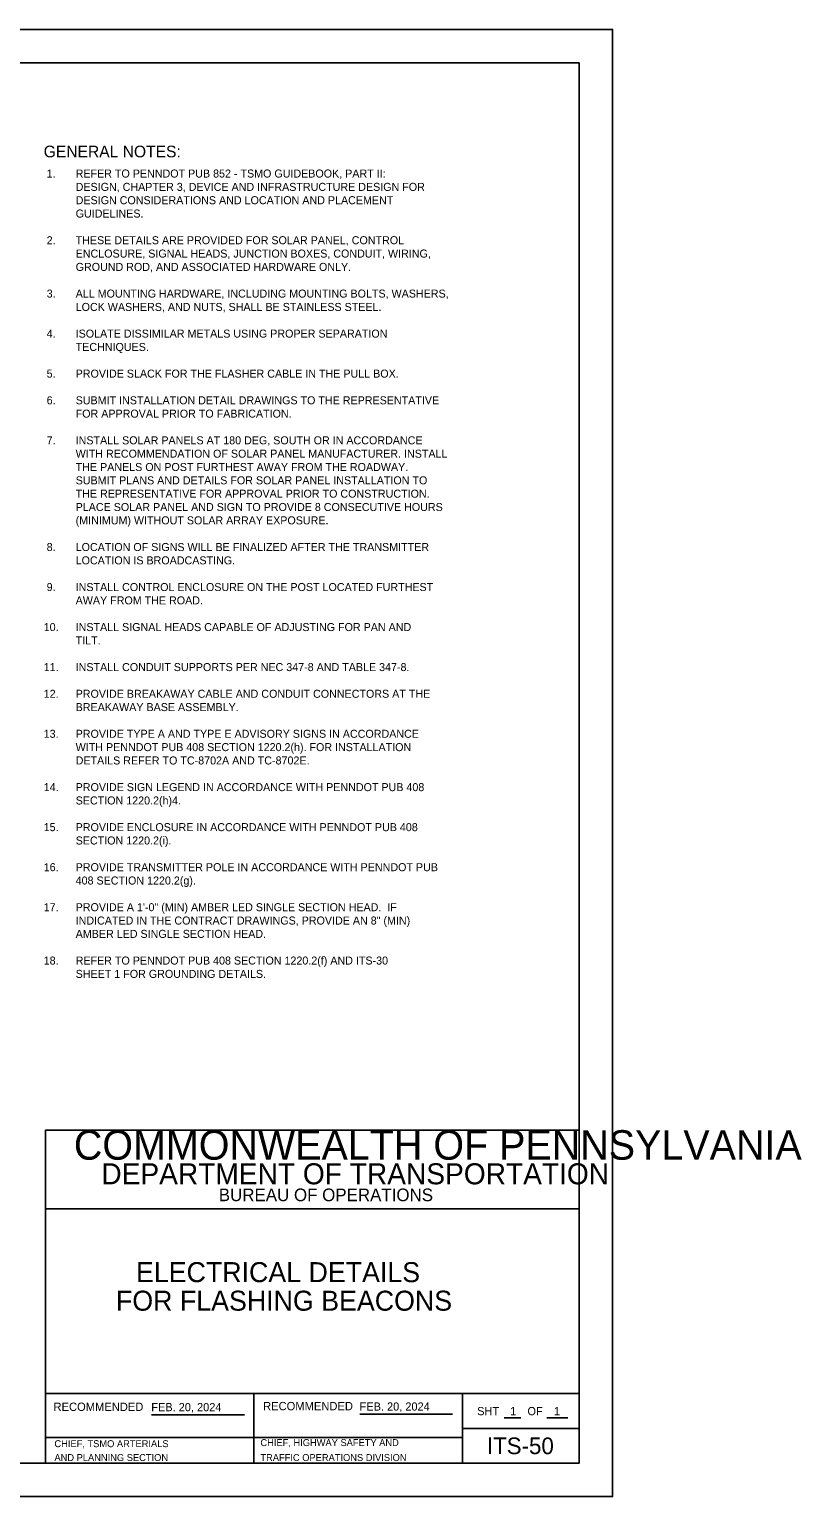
# Model space of a CAD drawing. Extents: x 1299104.6 to 1299141.5, y 239713.3 to 239735.3.
# Drawn here: x 1299129.88 to 1299141.46, y 239713.27 to 239735.27 of the extents above; entities that cross this region are included whole.
import ezdxf

# ---------------------------------------------------------------- set-up
doc = ezdxf.new("R2010")
doc.units = 0
for name, color, linetype in [('1', 7, 'Continuous'), ('2', 7, 'Continuous'), ('DIM TXT', 7, 'Continuous'), ('GS_noplot_1', 7, 'Continuous'), ('GS_plotshape_p', 7, 'Continuous'), ('Level 1', 7, 'Continuous'), ('PTEXT', 7, 'Continuous')]:
    doc.layers.add(name, color=color, linetype=linetype)

msp = doc.modelspace()

# ---------------------------------------------------------------- linework, layer by layer
at = {"layer": '1'}
for p, q in [((1299131.715, 239714.502), (1299133.105, 239714.502)), ((1299134.837, 239714.511), (1299136.226, 239714.511)), ((1299136.996, 239714.455), (1299137.248, 239714.455)), ((1299137.639, 239714.455), (1299137.953, 239714.455)), ((1299130.122, 239714.161), (1299133.247, 239714.161))]:
    msp.add_line(p, q, dxfattribs=at)
at = {"layer": 'GS_noplot_1'}
msp.add_lwpolyline([(1299130.122, 239714.821), (1299136.372, 239714.821), (1299136.372, 239713.773), (1299130.122, 239713.773)], close=True, dxfattribs=at)
at = {"layer": 'GS_plotshape_p'}
msp.add_lwpolyline([(1299104.622, 239735.273), (1299138.622, 239735.273), (1299138.622, 239713.273), (1299104.622, 239713.273)], close=True, dxfattribs=at)
at = {"layer": 'Level 1'}
for p, q in [((1299130.122, 239714.821), (1299138.122, 239714.821)), ((1299133.247, 239714.821), (1299133.247, 239713.773)), ((1299136.372, 239714.297), (1299138.122, 239714.297)), ((1299133.247, 239714.161), (1299136.372, 239714.161))]:
    msp.add_line(p, q, dxfattribs=at)
for points in [[(1299138.122, 239713.773), (1299106.122, 239713.773), (1299106.122, 239734.773), (1299138.122, 239734.773)], [(1299138.122, 239718.766), (1299130.122, 239718.766), (1299130.122, 239717.586), (1299138.122, 239717.586)], [(1299138.122, 239718.766), (1299130.122, 239718.766), (1299130.122, 239713.773), (1299138.122, 239713.773)]]:
    msp.add_lwpolyline(points, close=True, dxfattribs=at)

# ---------------------------------------------------------------- texts
at = {"layer": '1'}
for s, height, p in [('COMMONWEALTH OF PENNSYLVANIA', 0.44223, (1299130.549, 239718.325)), ('DEPARTMENT OF TRANSPORTATION', 0.31514, (1299130.961, 239717.956)), ('BUREAU OF OPERATIONS', 0.18955, (1299132.721, 239717.703)), ('RECOMMENDED', 0.125, (1299130.244, 239714.558)), ('FEB. 20, 2024', 0.12303, (1299131.709, 239714.554)), ('RECOMMENDED', 0.125, (1299133.385, 239714.568)), ('FEB. 20, 2024', 0.12303, (1299134.831, 239714.563)), ('CHIEF, TSMO ARTERIALS ', 0.10417, (1299130.258, 239714.015)), ('CHIEF, HIGHWAY SAFETY AND ', 0.10417, (1299133.345, 239714.031)), ('AND PLANNING SECTION', 0.10417, (1299130.258, 239713.807)), ('TRAFFIC OPERATIONS DIVISION', 0.10417, (1299133.345, 239713.807))]:
    msp.add_text(s, height=height, dxfattribs=at).set_placement(p)
at = {"layer": '2'}
for s, p in [('SHT', (1299136.593, 239714.494)), ('1', (1299137.087, 239714.494)), ('OF', (1299137.347, 239714.494)), ('1', (1299137.744, 239714.494))]:
    msp.add_text(s, height=0.123, dxfattribs=at).set_placement(p)
at = {"layer": 'DIM TXT'}
for s, p in [('REFER TO PENNDOT PUB 852 - TSMO GUIDEBOOK, PART II: ', (1299130.576, 239733.051)), ('DESIGN, CHAPTER 3, DEVICE AND INFRASTRUCTURE DESIGN FOR ', (1299130.576, 239732.851)), ('DESIGN CONSIDERATIONS AND LOCATION AND PLACEMENT ', (1299130.576, 239732.651)), ('GUIDELINES.', (1299130.576, 239732.451)), ('THESE DETAILS ARE PROVIDED FOR SOLAR PANEL, CONTROL ', (1299130.576, 239732.051)), ('ENCLOSURE, SIGNAL HEADS, JUNCTION BOXES, CONDUIT, WIRING, ', (1299130.576, 239731.851)), ('GROUND ROD, AND ASSOCIATED HARDWARE ONLY.', (1299130.576, 239731.651)), ('ALL MOUNTING HARDWARE, INCLUDING MOUNTING BOLTS, WASHERS, ', (1299130.576, 239731.251)), ('LOCK WASHERS, AND NUTS, SHALL BE STAINLESS STEEL. ', (1299130.576, 239731.051)), ('ISOLATE DISSIMILAR METALS USING PROPER SEPARATION ', (1299130.576, 239730.651)), ('TECHNIQUES.', (1299130.576, 239730.451)), ('PROVIDE SLACK FOR THE FLASHER CABLE IN THE PULL BOX. ', (1299130.576, 239730.051)), ('SUBMIT INSTALLATION DETAIL DRAWINGS TO THE REPRESENTATIVE ', (1299130.576, 239729.651)), ('FOR APPROVAL PRIOR TO FABRICATION. ', (1299130.576, 239729.451)), ('INSTALL SOLAR PANELS AT 180 DEG, SOUTH OR IN ACCORDANCE ', (1299130.576, 239729.051)), ('WITH RECOMMENDATION OF SOLAR PANEL MANUFACTURER. INSTALL ', (1299130.576, 239728.851)), ('THE PANELS ON POST FURTHEST AWAY FROM THE ROADWAY.  ', (1299130.576, 239728.651)), ('SUBMIT PLANS AND DETAILS FOR SOLAR PANEL INSTALLATION TO ', (1299130.576, 239728.451)), ('THE REPRESENTATIVE FOR APPROVAL PRIOR TO CONSTRUCTION. ', (1299130.576, 239728.251)), ('PLACE SOLAR PANEL AND SIGN TO PROVIDE 8 CONSECUTIVE HOURS ', (1299130.576, 239728.051)), ('(MINIMUM) WITHOUT SOLAR ARRAY EXPOSURE.', (1299130.576, 239727.851)), ('LOCATION OF SIGNS WILL BE FINALIZED AFTER THE TRANSMITTER ', (1299130.576, 239727.451)), ('LOCATION IS BROADCASTING. ', (1299130.576, 239727.251)), ('INSTALL CONTROL ENCLOSURE ON THE POST LOCATED FURTHEST ', (1299130.576, 239726.851)), ('AWAY FROM THE ROAD. ', (1299130.576, 239726.651)), ('INSTALL SIGNAL HEADS CAPABLE OF ADJUSTING FOR PAN AND ', (1299130.576, 239726.251)), ('TILT. ', (1299130.576, 239726.051)), ('INSTALL CONDUIT SUPPORTS PER NEC 347-8 AND TABLE 347-8. ', (1299130.576, 239725.651)), ('PROVIDE BREAKAWAY CABLE AND CONDUIT CONNECTORS AT THE ', (1299130.576, 239725.251)), ('BREAKAWAY BASE ASSEMBLY.', (1299130.576, 239725.051)), ('PROVIDE TYPE A AND TYPE E ADVISORY SIGNS IN ACCORDANCE ', (1299130.576, 239724.651)), ('WITH PENNDOT PUB 408 SECTION 1220.2(h). FOR INSTALLATION ', (1299130.576, 239724.451)), ('DETAILS REFER TO TC-8702A AND TC-8702E.', (1299130.576, 239724.251)), ('PROVIDE SIGN LEGEND IN ACCORDANCE WITH PENNDOT PUB 408 ', (1299130.576, 239723.851)), ('SECTION 1220.2(h)4.', (1299130.576, 239723.651)), ('PROVIDE ENCLOSURE IN ACCORDANCE WITH PENNDOT PUB 408 ', (1299130.576, 239723.251)), ('SECTION 1220.2(i).', (1299130.576, 239723.051)), ('408 SECTION 1220.2(g).', (1299130.576, 239722.451)), ('PROVIDE TRANSMITTER POLE IN ACCORDANCE WITH PENNDOT PUB ', (1299130.576, 239722.651)), ('PROVIDE A 1\'-0" (MIN) AMBER LED SINGLE SECTION HEAD.  IF ', (1299130.576, 239722.051)), ('INDICATED IN THE CONTRACT DRAWINGS, PROVIDE AN 8" (MIN) ', (1299130.576, 239721.851)), ('AMBER LED SINGLE SECTION HEAD.', (1299130.576, 239721.651)), ('REFER TO PENNDOT PUB 408 SECTION 1220.2(f) AND ITS-30 ', (1299130.576, 239721.251)), ('SHEET 1 FOR GROUNDING DETAILS.', (1299130.576, 239721.051))]:
    msp.add_text(s, height=0.12, dxfattribs=at).set_placement(p)
at = {"layer": 'PTEXT'}
for s, height, p in [('GENERAL NOTES:', 0.175, (1299130.097, 239733.354)), (' 1.', 0.12, (1299130.097, 239733.051)), (' 2.', 0.12, (1299130.097, 239732.051)), (' 3.', 0.12, (1299130.097, 239731.251)), (' 4. ', 0.12, (1299130.097, 239730.651)), (' 5.', 0.12, (1299130.097, 239730.051)), (' 6.', 0.12, (1299130.097, 239729.651)), (' 7.', 0.12, (1299130.097, 239729.051)), (' 8.', 0.12, (1299130.097, 239727.451)), (' 9.', 0.12, (1299130.097, 239726.851)), ('10.', 0.12, (1299130.097, 239726.251)), ('11.', 0.12, (1299130.097, 239725.651)), ('12.', 0.12, (1299130.097, 239725.251)), ('13.', 0.12, (1299130.097, 239724.651)), ('14.', 0.12, (1299130.097, 239723.851)), ('15.', 0.12, (1299130.097, 239723.251)), ('16.', 0.12, (1299130.097, 239722.651)), ('17.', 0.12, (1299130.097, 239722.051)), ('18.', 0.12, (1299130.097, 239721.251)), ('ELECTRICAL DETAILS', 0.3, (1299131.48, 239716.489)), ('FOR FLASHING BEACONS', 0.3, (1299131.18, 239716.061)), ('ITS-50', 0.25, (1299136.739, 239713.91))]:
    msp.add_text(s, height=height, dxfattribs=at).set_placement(p)

doc.saveas('drawing.dxf')
